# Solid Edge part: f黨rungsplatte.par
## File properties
Title: Führungsplatte
Subject: Schmiege
Author: rauh
Template: Normal.par
Last saved by: ra-tv
Revision: 4
Application: Solid Edge
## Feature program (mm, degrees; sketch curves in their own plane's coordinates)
sketch for "unnamed Protrusion 1" plane through (0, 0, 0) normal (0, 0, 1) x-axis (1, 0, 0)
  line (-12.5, -12.5) -> (12.5, -12.5)
  line (12.5, -12.5) -> (12.5, 12.5)
  line (12.5, 12.5) -> (-12.5, 12.5)
  line (-12.5, 12.5) -> (-12.5, -12.5)
extrude "unnamed Protrusion 1" add finite 5 symmetric
sketch for "unnamed Cutout 1" #1 plane through (0, 0, 2.5) normal (0, 0, 1) x-axis (1, 0, 0)
  circle centre (-5.5, -5.5) radius 2
sketch for "unnamed Cutout 1" #2 plane through (0, 0, 2.5) normal (0, 0, 1) x-axis (1, 0, 0)
  circle centre (5.5, 5.5) radius 2
extrude "unnamed Cutout 1" cut finite 95.25 symmetric
sketch for "unnamed Hole 1" plane through (0, 0, 2.5) normal (0, 0, 1) x-axis (1, 0, 0)
hole "unnamed Hole 1" through
